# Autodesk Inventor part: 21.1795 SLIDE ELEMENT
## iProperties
Created: 2007-05
Part Number: 21.1795 SLIDE ELEMENT
Material: UHMW, Black
Document SubType Name: Modeling
Designer: Andy Moles
Density: 0.94 g/cm^3
Author: Andy Moles
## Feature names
1. Extrusion1
2. Extrusion2
3. Extrusion3
4. Extrusion4
